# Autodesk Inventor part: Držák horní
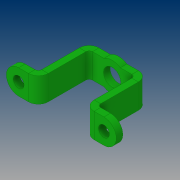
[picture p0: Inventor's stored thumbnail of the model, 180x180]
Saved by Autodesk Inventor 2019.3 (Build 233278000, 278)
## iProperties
Created: 2019-02
Part Number: Držák horní
Material: Ocel, legovaná
Document SubType Name: Plech
Designer: B-hon
Density: 7.73 g/cm^3
Sheet Metal Rule: Výchozí_mm
Appearance: Tmavě zelená
Author: B-hon
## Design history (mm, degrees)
node "Plocha1"
  sketch "Náčrt1"
    geometry: L1 (-18, 7.5)-(18, 7.5); L2 (18, 7.5)-(18, -7.5); L3 (18, -7.5)-(-18, -7.5); L4 (-18, -7.5)-(-18, 7.5); L5 (-18, 7.5)-(18, -7.5); L6 (18, 7.5)-(-18, -7.5); 1 further point
    constraints: 12 end point, 2 midpoint, 2 parallel, 1 horizontal, 1 perpendicular
    dimensions: "d0" = 36 distance of L2.end L3.end; "d1" = 15 distance of L1.end L2.end
node "Obruba3"
node "Obruba4"
sketch "Náčrt6"
  geometry: L1 (-67, 15)-(-53.5, 15) reference; L2 (0, 15)-(0, 0) reference; L3 (-67, 0)-(-67, 15) reference; 3 further points
  constraints: 1 horizontal alignment
  dimensions: "d43" = 7.5 distance from line of L1 point (-59.5, 7.5); "d44" = 67 distance between parallel lines of L2 L3 (derived); "d45" = 52 distance of point (-7.5, 7.5) point (-59.5, 7.5); "d46" = 7.5 distance from line of L2 point (-7.5, 7.5) (= -0.5 x d45 + 0.5 x d44)
hole "Díra1" sketch "Náčrt6" at (-59.5, 7.5), (-7.5, 7.5) diameter "d47" = 6.6; stored, may be unused: countersink angle "d51" = 90 deg, drill point angle "d53" = 118 deg; dims "d48" = 12, "d49" = 6, "d50" = 2, "d52" = 4 (= Tloušťka)
fillet "Zaoblení1" dims "d54" = 7.5
sketch "Náčrt7"
  geometry: L1 (12, 7.5)-(-12, 7.5) reference; L2 (-12, 7.5)-(-12, -7.5) reference; 2 further points
  dimensions: "d55" = 7.5 distance from line of L1 point (0, 0); "d56" = 12 distance from line of L2 point (0, 0)
hole "Díra2" sketch "Náčrt7" at (0, 0) diameter "d57" = 10.5; stored, may be unused: countersink angle "d61" = 90 deg, drill point angle "d63" = 118 deg; dims "d58" = 12, "d59" = 6, "d60" = 2, "d62" = 4 (= Tloušťka)
sketch "Náčrt8"
  geometry: C1 r 9 at (0, 0); C2 r 6.14 at (0, 0); 1 further point
  constraints: 2 centre point, 2 coincident
  dimensions: "d64" = 18 diameter of C1
extrude "Vysunutí1" join sketch "Náčrt8" distance "d65" = 4; taper "d66" = 0 deg
node "Těleso1"
feature "Deska1" dims "d2" = 4 (= Tloušťka)
sketch "Náčrt4"
  geometry: L1 through (-7.5, 0) direction (1, 9.06e-33); L2 through (0, 17.5) direction (-9.39e-33, 1); L3 (0, 35)-(-15, 35); L4 (-15, 35)-(-15, 0)
  constraints: 6 end point, 1 horizontal, 1 perpendicular, 1 vertical
feature "Deska4" dims "d2" = 4 (= Tloušťka), "d23" = 4 (= ŠířkaVýštipu), "d24" = 2 (= HloubkaVýštipu), "d25" = 8 (= MinimálníZbytek), "d26" = 4 (= PřechodovýPoloměr), "d27" = 35, "d28" = 90 deg, "d29" = 2, "d30" = 16 (= VelikostRohovéhoVýštipu), "d31" = 4 (= VelikostMezery), "d32" = 4 (= VelikostJacobihoPoloměru), "MezeraVystřižení" = 0.01
feature "Ohyb3" dims "d2" = 4 (= Tloušťka), "d23" = 4 (= ŠířkaVýštipu), "d24" = 2 (= HloubkaVýštipu), "d25" = 8 (= MinimálníZbytek), "d26" = 4 (= PřechodovýPoloměr), "d27" = 35, "d28" = 90 deg, "d29" = 2, "MezeraVystřižení" = 0.01
feature "Roh3" dims "d27" = 35, "d28" = 90 deg, "d30" = 16 (= VelikostRohovéhoVýštipu), "d31" = 4 (= VelikostMezery), "d32" = 4 (= VelikostJacobihoPoloměru)
sketch "Náčrt5"
  geometry: L1 through (0, -7.5) direction (-5.92e-16, 1); L2 through (-9.75, 0) direction (-1, -4.55e-16); L3 (-19.5, 0)-(-19.5, -15); L4 (-19.5, -15)-(0, -15)
  constraints: 6 end point, 1 horizontal, 1 perpendicular, 1 vertical
feature "Deska5" dims "d2" = 4 (= Tloušťka), "d33" = 4 (= ŠířkaVýštipu), "d34" = 2 (= HloubkaVýštipu), "d35" = 8 (= MinimálníZbytek), "d36" = 4 (= PřechodovýPoloměr), "d37" = 19.5, "d38" = 90 deg, "d39" = 2, "d40" = 16 (= VelikostRohovéhoVýštipu), "d41" = 4 (= VelikostMezery), "d42" = 4 (= VelikostJacobihoPoloměru), "MezeraVystřižení" = 0.01
feature "Ohyb4" dims "d2" = 4 (= Tloušťka), "d33" = 4 (= ŠířkaVýštipu), "d34" = 2 (= HloubkaVýštipu), "d35" = 8 (= MinimálníZbytek), "d36" = 4 (= PřechodovýPoloměr), "d37" = 19.5, "d38" = 90 deg, "d39" = 2, "MezeraVystřižení" = 0.01
feature "Roh4" dims "d37" = 19.5, "d38" = 90 deg, "d40" = 16 (= VelikostRohovéhoVýštipu), "d41" = 4 (= VelikostMezery), "d42" = 4 (= VelikostJacobihoPoloměru)
other parameters: "Tloušťka" = 4 (derived), "KSoučinitel" = 4.4, "PoloměrOhybu" = 4 (= Tloušťka), "ŠířkaVýštipu" = 4 (= Tloušťka), "HloubkaVýštipu" = 2 (= 0.5 x Tloušťka), "VelikostRohovéhoVýštipu" = 16 (= 4 x Tloušťka), "MinimálníZbytek" = 8 (= 2 x Tloušťka), "PřechodovýPoloměr" = 4 (= PoloměrOhybu), "VelikostJacobihoPoloměru" = 4 (= PoloměrOhybu), "VelikostMezery" = 4 (= Tloušťka)
